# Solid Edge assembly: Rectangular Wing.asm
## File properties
Author: hullrw
Template: ansi assembly.asm
Last saved by: hullrw
Revision: 8
Application: Solid Edge
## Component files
Payload Connection.par
Shear Web.par
Shear Web 6.25.par
Cap.par
Shear Web 2.375.par
Shear Web CENTER.par
3D_Rect_Rib.par
Stringer.par
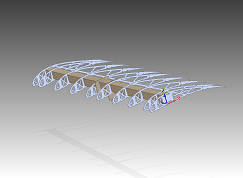
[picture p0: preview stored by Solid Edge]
